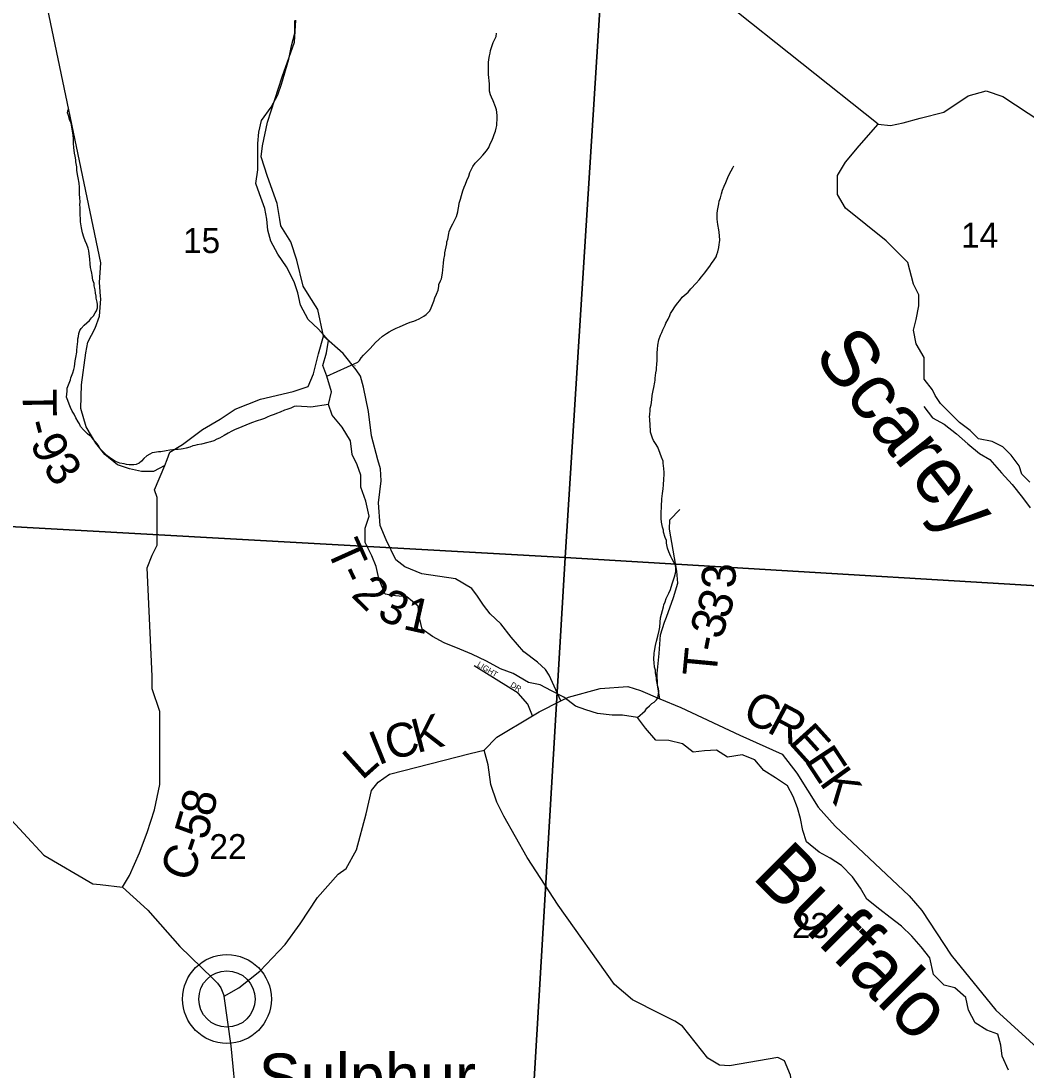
# Model space of a CAD drawing. Extents: x 0 to 34, y 0 to 22.
# Drawn here: x 6.056 to 7.74, y 18.037 to 19.794 of the extents above; entities that cross this region are included whole.
import ezdxf

# ---------------------------------------------------------------- set-up
doc = ezdxf.new("R2010")
doc.units = 0
for name, color, linetype in [('GM_X_County_Road', 7, 'Continuous'), ('GM_X_County_Road_Text', 7, 'Continuous'), ('GM_X_Minor_River', 7, 'Continuous'), ('GM_X_Minor_River_Text', 7, 'Continuous'), ('GM_X_Section', 7, 'Continuous'), ('GM_X_Section_Text', 7, 'Continuous'), ('GM_X_Township_Road', 7, 'Continuous'), ('GM_X_Township_Road_Text', 7, 'Continuous'), ('GM_X_Township_ROW', 7, 'Continuous'), ('GM_X_Township_Subdivision', 7, 'Continuous'), ('GM_X_Township_Subdivision_Text', 7, 'Continuous'), ('GM_X_Unincorporated', 7, 'Continuous'), ('GM_X_Unincorporated_Location', 7, 'Continuous'), ('GM_X_Unincorporated_Text', 7, 'Continuous')]:
    doc.layers.add(name, color=color, linetype=linetype)

msp = doc.modelspace()

# ---------------------------------------------------------------- linework, layer by layer
at = {"layer": 'GM_X_County_Road'}
for points in [[(6.2266, 18.3431), (6.238, 18.3629), (6.2549, 18.4009), (6.2675, 18.4347), (6.2802, 18.4727), (6.2886, 18.5149), (6.2886, 18.6373), (6.276, 18.6753), (6.276, 18.6964), (6.2675, 18.8779), (6.276, 18.899), (6.2844, 18.9159), (6.2844, 18.9961), (6.2802, 19.0087), (6.2972, 19.0494), (6.3013, 19.0594), (6.3055, 19.072), (6.3266, 19.0847), (6.3604, 19.11), (6.3899, 19.1269), (6.4152, 19.1438), (6.4574, 19.1607), (6.5123, 19.1733), (6.5376, 19.1818), (6.5461, 19.2029), (6.5545, 19.2366), (6.5629, 19.2661), (6.5536, 19.3108), (6.5392, 19.3335), (6.5289, 19.35), (6.5185, 19.3933), (6.5082, 19.4243), (6.4917, 19.4511), (6.4897, 19.4614), (6.4855, 19.4882), (6.469, 19.5336), (6.4587, 19.5666), (6.4608, 19.5851), (6.469, 19.6243), (6.4938, 19.7006), (6.5144, 19.7584), (6.5165, 19.7955)], [(6.1891, 18.3474), (6.2266, 18.3431), (6.2622, 18.3107), (6.2687, 18.3048), (6.3223, 18.2435), (6.377, 18.1905), (6.3855, 18.1823), (6.3913, 18.1746), (6.3965, 18.1604), (6.4212, 18.1743), (6.4566, 18.2027), (6.4991, 18.247), (6.5239, 18.2815), (6.5531, 18.3258), (6.5876, 18.3648), (6.6009, 18.3746), (6.6186, 18.4056), (6.6346, 18.4658), (6.6434, 18.5048), (6.6549, 18.519), (6.6735, 18.5323), (6.809, 18.5668), (6.8321, 18.5724), (6.8533, 18.5943), (6.9129, 18.6301), (6.9241, 18.6368), (6.9604, 18.655), (6.9737, 18.6616), (7.0268, 18.6758), (7.0729, 18.6793), (7.0941, 18.6723), (7.1264, 18.6587), (7.1614, 18.6439), (7.2606, 18.5979), (7.3315, 18.566), (7.3562, 18.5341), (7.3917, 18.4774), (7.42, 18.4456), (7.544, 18.3286), (7.5652, 18.3038), (7.6148, 18.2294), (7.6892, 18.1373), (7.7707, 18.0629)], [(7.3497, 17.9972), (7.3496, 17.9977), (7.3453, 18.028), (7.3354, 18.0523), (7.3241, 18.058), (7.243, 18.0436), (7.2267, 18.0451), (7.207, 18.0569), (7.1646, 18.1101), (7.1517, 18.1188), (7.126, 18.1314), (7.0809, 18.1546), (7.0506, 18.18), (6.9559, 18.313), (6.904, 18.3931), (6.865, 18.4619), (6.8533, 18.4858), (6.8431, 18.5151), (6.8389, 18.5481), (6.8321, 18.5724)], [(6.0263, 18.4702), (6.0945, 18.3967), (6.1768, 18.3489), (6.1891, 18.3474)], [(6.4177, 17.9792), (6.4082, 18.0772), (6.3965, 18.1604)]]:
    msp.add_lwpolyline(points, dxfattribs=at)
at = {"layer": 'GM_X_Minor_River'}
for points in [[(7.0639, 18.6314), (7.0465, 18.6315), (7.0223, 18.6338), (7.0026, 18.64), (6.9852, 18.6461), (6.9656, 18.6614), (6.9452, 18.6721), (6.9263, 18.682), (6.9066, 18.6859), (6.8809, 18.7012), (6.8597, 18.7088), (6.8363, 18.7218), (6.8114, 18.7333), (6.7917, 18.7417), (6.7653, 18.7524), (6.7456, 18.7631), (6.7282, 18.7754), (6.7238, 18.7944), (6.7216, 18.8141), (6.7027, 18.8294), (6.6838, 18.831), (6.6664, 18.834), (6.6559, 18.8599), (6.6514, 18.8804), (6.6439, 18.8979), (6.6327, 18.9207), (6.6328, 18.9443), (6.6397, 18.9648), (6.6337, 18.9898), (6.6255, 19.0134), (6.6256, 19.0331), (6.6196, 19.0506), (6.6113, 19.0681), (6.6084, 19.0909), (6.5941, 19.1137), (6.5775, 19.1335), (6.5715, 19.1518), (6.5762, 19.173), (6.5687, 19.1989), (6.562, 19.2171), (6.5681, 19.2383), (6.5712, 19.2588), (6.5546, 19.2779), (6.5373, 19.2939), (6.5245, 19.3182), (6.5201, 19.3387), (6.5141, 19.357), (6.5013, 19.3821), (6.4863, 19.4034), (6.475, 19.4254), (6.4698, 19.4437), (6.4683, 19.4619), (6.4646, 19.4801), (6.4556, 19.5045), (6.4496, 19.522), (6.4528, 19.5447), (6.453, 19.5887), (6.4545, 19.6077), (6.4592, 19.6274), (6.4752, 19.6494), (6.4866, 19.6706), (6.4928, 19.6881), (6.505, 19.7298), (6.5097, 19.7525), (6.5151, 19.7738), (6.5152, 19.795)], [(6.8409, 19.7354), (6.8422, 19.7399), (6.843, 19.7445), (6.845, 19.7513), (6.8474, 19.758), (6.8521, 19.7678), (6.853, 19.7735)], [(6.5687, 19.1989), (6.6205, 19.2223), (6.6233, 19.2256), (6.6264, 19.2298), (6.6302, 19.2342), (6.6337, 19.238), (6.6414, 19.2455), (6.6457, 19.2503), (6.6503, 19.2552), (6.6557, 19.2604), (6.6618, 19.266), (6.6684, 19.2704), (6.673, 19.2734), (6.6779, 19.2764), (6.6848, 19.2793), (6.6901, 19.2819), (6.7016, 19.287), (6.7085, 19.2895), (6.7142, 19.2913), (6.7184, 19.2931), (6.7233, 19.2953), (6.7314, 19.2994), (6.7348, 19.3024), (6.7414, 19.3083), (6.7437, 19.3136), (6.7457, 19.3189), (6.7481, 19.3249), (6.7497, 19.3302), (6.7521, 19.3363), (6.7549, 19.3434), (6.7561, 19.3491), (6.7565, 19.3525), (6.7593, 19.3589), (6.7605, 19.3623), (6.7622, 19.3714), (6.763, 19.3771), (6.7635, 19.3828), (6.764, 19.3881), (6.7649, 19.3945), (6.7661, 19.4021), (6.7662, 19.4055), (6.7674, 19.4108), (6.7695, 19.4206), (6.7695, 19.4241), (6.7711, 19.4286), (6.7732, 19.438), (6.7736, 19.4415), (6.7768, 19.449), (6.7795, 19.4543), (6.7823, 19.4599), (6.7858, 19.4663), (6.787, 19.4705), (6.7879, 19.4746), (6.7887, 19.4784), (6.7895, 19.4841), (6.7904, 19.4886), (6.7924, 19.4954), (6.7944, 19.5019), (6.7964, 19.5094), (6.7988, 19.5155), (6.8012, 19.5207), (6.8032, 19.5268), (6.8063, 19.5343), (6.8083, 19.54), (6.8107, 19.5445), (6.8134, 19.5502), (6.8173, 19.5558), (6.8243, 19.5629), (6.8301, 19.5692), (6.8362, 19.5763), (6.8401, 19.582), (6.8425, 19.588), (6.8449, 19.5933), (6.8472, 19.5989), (6.8492, 19.6038), (6.8512, 19.6095), (6.8524, 19.6144), (6.8533, 19.619), (6.8534, 19.6231), (6.8538, 19.6285), (6.8539, 19.6353), (6.8537, 19.6414), (6.8526, 19.6452), (6.8512, 19.6505), (6.8472, 19.6601), (6.8443, 19.6662), (6.8428, 19.6704), (6.8414, 19.6765), (6.8412, 19.683), (6.8409, 19.689), (6.8396, 19.7043), (6.8394, 19.7115), (6.8396, 19.7244), (6.8401, 19.7293), (6.8409, 19.7354)], [(6.1497, 19.2427), (6.1502, 19.248), (6.1515, 19.2571), (6.1516, 19.2617), (6.1524, 19.2658), (6.1532, 19.2704), (6.1548, 19.2753), (6.1572, 19.2787), (6.1622, 19.2843), (6.1664, 19.2884), (6.1711, 19.2925), (6.1745, 19.297), (6.1776, 19.3003), (6.1807, 19.3049), (6.1827, 19.3086), (6.1843, 19.3135), (6.1844, 19.3192), (6.1837, 19.323), (6.1823, 19.3295), (6.182, 19.3329), (6.1813, 19.3379), (6.1803, 19.3436), (6.1789, 19.3505), (6.1786, 19.3543), (6.1768, 19.36), (6.1754, 19.368), (6.1751, 19.3718), (6.1737, 19.3764), (6.1726, 19.3813), (6.1723, 19.387), (6.1717, 19.395), (6.1701, 19.4091), (6.169, 19.4133), (6.1665, 19.4194), (6.1636, 19.4259), (6.1614, 19.432), (6.1592, 19.4389), (6.1575, 19.4473), (6.1562, 19.4576), (6.1562, 19.4617), (6.1556, 19.4705), (6.1554, 19.4819), (6.1551, 19.4857), (6.1552, 19.4914), (6.155, 19.4971), (6.1543, 19.5043), (6.1541, 19.5119), (6.1541, 19.5157), (6.1535, 19.5225), (6.1522, 19.5313), (6.1511, 19.537), (6.1501, 19.5442), (6.1498, 19.5499), (6.1481, 19.5583), (6.1481, 19.5617), (6.1471, 19.5678), (6.1461, 19.5728), (6.1447, 19.5823), (6.1445, 19.5888), (6.1442, 19.596), (6.1436, 19.6025), (6.1426, 19.6097), (6.1408, 19.6196), (6.1405, 19.623), (6.1383, 19.6272), (6.1358, 19.6356), (6.1344, 19.6402), (6.1352, 19.6459)], [(7.1222, 19.232), (7.1219, 19.2381), (7.1224, 19.2442), (7.1229, 19.251), (7.125, 19.2597), (7.1277, 19.2676), (7.1297, 19.2721), (7.1313, 19.2767), (7.1356, 19.2846), (7.1364, 19.288), (7.1403, 19.2944), (7.1435, 19.3008), (7.1443, 19.3042), (7.1478, 19.3091), (7.1517, 19.3151), (7.1563, 19.3214), (7.1602, 19.3259), (7.1641, 19.3316), (7.1741, 19.3397), (7.1784, 19.3454), (7.1872, 19.3547), (7.1923, 19.3607), (7.1961, 19.3656), (7.2016, 19.3723), (7.2062, 19.3783), (7.2101, 19.3836), (7.2132, 19.3877), (7.2175, 19.3941), (7.2206, 19.399), (7.2218, 19.4027), (7.2238, 19.4076), (7.2254, 19.4148), (7.2259, 19.4194), (7.2267, 19.4232), (7.2271, 19.4269), (7.2265, 19.4342), (7.2259, 19.4403), (7.2256, 19.4441), (7.2234, 19.4532), (7.2228, 19.4623), (7.2225, 19.4673), (7.2226, 19.4718), (7.2231, 19.4764), (7.2256, 19.4877), (7.226, 19.4923), (7.228, 19.4979), (7.23, 19.5044), (7.2316, 19.5104), (7.234, 19.5172), (7.2368, 19.5236), (7.2415, 19.5349), (7.2459, 19.5428), (7.2486, 19.5481), (7.2505, 19.5515)], [(6.5715, 19.1518), (6.542, 19.1472), (6.5355, 19.1477), (6.5261, 19.1483), (6.5181, 19.1488), (6.5139, 19.1485), (6.5082, 19.1455), (6.5014, 19.1434), (6.4979, 19.1419), (6.4903, 19.139), (6.4842, 19.1364), (6.4804, 19.135), (6.4739, 19.1324), (6.4686, 19.1303), (6.4644, 19.1284), (6.459, 19.1266), (6.4522, 19.1245), (6.4426, 19.1208), (6.4327, 19.1172), (6.4194, 19.1113), (6.4148, 19.1095), (6.4094, 19.1069), (6.4033, 19.1036), (6.3964, 19.0999), (6.3888, 19.0955), (6.3842, 19.0933), (6.3796, 19.0907), (6.3735, 19.0889), (6.3693, 19.0879), (6.3587, 19.0854), (6.3515, 19.084), (6.3476, 19.0829), (6.3442, 19.0822), (6.3393, 19.0804), (6.3328, 19.0786), (6.3282, 19.0775), (6.3244, 19.0768), (6.3195, 19.0765), (6.315, 19.0762), (6.3104, 19.0759), (6.3059, 19.0753), (6.2994, 19.0738), (6.2903, 19.0725), (6.2869, 19.0722), (6.28, 19.0711), (6.2762, 19.0704), (6.272, 19.0686), (6.267, 19.0656), (6.262, 19.0612), (6.2582, 19.0567), (6.254, 19.0533), (6.2494, 19.0511), (6.2452, 19.0508), (6.2376, 19.0506), (6.2331, 19.051), (6.2289, 19.0522), (6.2221, 19.0535), (6.2165, 19.0555), (6.2127, 19.0574), (6.2067, 19.061), (6.2023, 19.0648), (6.1967, 19.0695), (6.1926, 19.0734), (6.1889, 19.0776), (6.1867, 19.0818), (6.1841, 19.086), (6.1807, 19.0899), (6.177, 19.0937), (6.1744, 19.0972), (6.1711, 19.0995), (6.1677, 19.1026), (6.1644, 19.1061), (6.161, 19.1092), (6.1558, 19.115), (6.1544, 19.1192), (6.1522, 19.1226), (6.1481, 19.1295), (6.1452, 19.1353), (6.1422, 19.1407), (6.1393, 19.1468), (6.1371, 19.1521), (6.1346, 19.1586), (6.1328, 19.164), (6.1337, 19.1742), (6.1338, 19.1788), (6.1358, 19.1844), (6.139, 19.1931), (6.1398, 19.1965), (6.1434, 19.2045), (6.145, 19.2105), (6.1458, 19.2147), (6.1467, 19.2196), (6.1471, 19.2245), (6.148, 19.2302), (6.1497, 19.2393), (6.1497, 19.2427)], [(7.0889, 18.6275), (7.1019, 18.6387), (7.1046, 18.6432), (7.1092, 18.647), (7.1131, 18.6507), (7.1169, 18.6533), (7.1208, 18.657), (7.1231, 18.6604), (7.1244, 18.6668), (7.1248, 18.6714), (7.1245, 18.6752), (7.1234, 18.6794), (7.122, 18.6847), (7.121, 18.6904), (7.1207, 18.6939), (7.1193, 18.7022), (7.119, 18.7064), (7.1176, 18.7118), (7.117, 18.7194), (7.1167, 18.7243), (7.1172, 18.7353), (7.1177, 18.7387), (7.119, 18.7478), (7.121, 18.7554), (7.1234, 18.7637), (7.1255, 18.7732), (7.1263, 18.7789), (7.1269, 18.7872), (7.1277, 18.7944), (7.1294, 18.8005), (7.1326, 18.8126), (7.1334, 18.8163), (7.1354, 18.8212), (7.137, 18.8269), (7.1413, 18.8356), (7.1441, 18.842), (7.1473, 18.8514), (7.1489, 18.8563), (7.1513, 18.8631), (7.1529, 18.8692), (7.1534, 18.8726), (7.1535, 18.8787), (7.152, 18.884), (7.1502, 18.8875), (7.1473, 18.8925), (7.1451, 18.897), (7.1418, 18.9047), (7.1396, 18.9112), (7.1379, 18.9196), (7.1376, 18.9241), (7.1354, 18.9287), (7.1329, 18.9379), (7.1326, 18.9413), (7.1312, 18.9459), (7.1294, 18.9543), (7.1288, 18.9607), (7.1285, 18.9653), (7.129, 18.9714), (7.1295, 18.9793), (7.1292, 18.985), (7.13, 18.9892), (7.1301, 18.9934), (7.131, 19.0025), (7.1319, 19.0104), (7.1328, 19.0173), (7.133, 19.0264), (7.1335, 19.0343), (7.1335, 19.0378), (7.1333, 19.0446), (7.1323, 19.0534), (7.132, 19.0568), (7.1295, 19.0633), (7.1273, 19.0694), (7.1229, 19.0801), (7.1192, 19.0862), (7.1159, 19.0916), (7.1141, 19.0954), (7.1123, 19.1), (7.1109, 19.1054), (7.1109, 19.1088), (7.1103, 19.116), (7.1097, 19.1274), (7.1094, 19.1308), (7.1095, 19.135), (7.1104, 19.1418), (7.1104, 19.1456), (7.1117, 19.1513), (7.113, 19.1596), (7.1139, 19.1668), (7.1155, 19.1748), (7.1164, 19.1801), (7.118, 19.1888), (7.1185, 19.1922), (7.1189, 19.196), (7.1194, 19.2002), (7.1198, 19.2047), (7.1207, 19.2096), (7.1207, 19.2131), (7.1216, 19.2184), (7.1221, 19.2259), (7.1222, 19.232)], [(6.6161, 19.2167), (6.6156, 19.2165)], [(7.5689, 19.1482), (7.5833, 19.1292), (7.6029, 19.1185), (7.6233, 19.1025), (7.6422, 19.0857), (7.6618, 19.0697), (7.6792, 19.0597), (7.6987, 19.0369), (7.7168, 19.0178), (7.7342, 18.9958), (7.747, 18.9783)], [(7.7105, 18.0366), (7.7, 18.0602), (7.6978, 18.0784), (7.6926, 18.0967), (7.6744, 18.1036), (7.6548, 18.1158), (7.6435, 18.1371), (7.639, 18.1584), (7.6209, 18.1744), (7.6028, 18.1791), (7.5847, 18.1966), (7.5787, 18.2247), (7.5644, 18.243), (7.5486, 18.2613), (7.5312, 18.2781), (7.5124, 18.2926), (7.495, 18.3056), (7.4731, 18.3231), (7.4626, 18.3414), (7.449, 18.3604), (7.4309, 18.3795), (7.412, 18.3917), (7.3932, 18.4016), (7.372, 18.4192), (7.366, 18.4382), (7.3623, 18.458), (7.3571, 18.4762), (7.3496, 18.4952), (7.3406, 18.5127), (7.3202, 18.5265), (7.3006, 18.5387), (7.2855, 18.5562), (7.2643, 18.5646), (7.2401, 18.5609), (7.2212, 18.5724), (7.2015, 18.5717), (7.1826, 18.5695), (7.1644, 18.5832), (7.1417, 18.5886), (7.1198, 18.5894), (7.1024, 18.6093), (7.0889, 18.6275), (7.0639, 18.6314)]]:
    msp.add_lwpolyline(points, dxfattribs=at)
at = {"layer": 'GM_X_Section'}
for points in [[(7.0324, 19.92), (6.9681, 18.8952), (5.8561, 18.9573), (5.9246, 19.9867)], [(8.1212, 19.8553), (8.0664, 18.8297), (6.9681, 18.8952), (7.0324, 19.92)], [(5.8561, 18.9573), (6.9681, 18.8952), (6.9079, 17.8893), (5.7907, 17.959)], [(6.9681, 18.8952), (8.0664, 18.8297), (8.012, 17.8219), (6.9079, 17.8893)]]:
    msp.add_lwpolyline(points, close=True, dxfattribs=at)
at = {"layer": 'GM_X_Township_Road'}
for points in [[(7.7466, 19.0215), (7.733, 19.0352), (7.7284, 19.0488), (7.7148, 19.067), (7.7012, 19.0806), (7.683, 19.0897), (7.6602, 19.0942), (7.6466, 19.1079), (7.6284, 19.1215), (7.5966, 19.1533), (7.5875, 19.1669), (7.583, 19.176), (7.5694, 19.1942), (7.5694, 19.2306), (7.5557, 19.2533), (7.5512, 19.276), (7.5557, 19.2942), (7.5603, 19.3169), (7.5603, 19.3351), (7.5512, 19.3532), (7.5421, 19.3896), (7.5058, 19.4259), (7.4376, 19.4805), (7.4239, 19.5032), (7.4239, 19.535), (7.4376, 19.5577), (7.4603, 19.585), (7.4921, 19.6213)], [(6.2972, 19.0494), (6.2784, 19.0396), (6.2583, 19.0392), (6.2383, 19.0441), (6.2182, 19.0506), (6.197, 19.0677), (6.1818, 19.087), (6.1652, 19.114), (6.1568, 19.1447), (6.1576, 19.1846), (6.1648, 19.2381), (6.1682, 19.256), (6.1807, 19.2795), (6.1879, 19.2996), (6.1898, 19.3285), (6.1894, 19.3332)], [(6.9604, 18.655), (6.9412, 18.6981), (6.9348, 18.7079), (6.9215, 18.7201), (6.8984, 18.7376), (6.8772, 18.7619), (6.8602, 18.7843), (6.8424, 18.801), (6.831, 18.8154), (6.8212, 18.8306), (6.8117, 18.8435), (6.7844, 18.8598), (6.7276, 18.8682), (6.6992, 18.8796), (6.6844, 18.8914), (6.6678, 18.9252), (6.6579, 18.9487), (6.6553, 18.9867), (6.6598, 19.0235), (6.6587, 19.044), (6.6542, 19.0592), (6.6436, 19.0991), (6.6383, 19.1397), (6.6303, 19.1807), (6.625, 19.1989), (6.6178, 19.2095), (6.5962, 19.2369), (6.5629, 19.2661)], [(7.1375, 18.7955), (7.1494, 18.8283), (7.1569, 18.8526), (7.1549, 18.8724), (7.1425, 18.9429), (7.1432, 18.9585), (7.1598, 18.9757)], [(7.1264, 18.6587), (7.1224, 18.6816), (7.122, 18.7009), (7.1252, 18.7348), (7.1274, 18.7659), (7.1345, 18.7872), (7.1375, 18.7954), (7.1375, 18.7955)]]:
    msp.add_lwpolyline(points, dxfattribs=at)
at = {"layer": 'GM_X_Township_ROW'}
for points in [[(7.4921, 19.6213), (7.2363, 19.8245), (6.9655, 20.0235), (6.7261, 20.2643), (6.563, 20.3945), (6.5017, 20.4356)], [(6.1894, 19.3332), (6.1876, 19.3562), (6.1898, 19.3892), (6.0906, 19.8649), (6.1237, 19.8842), (6.1299, 19.8887)], [(7.4921, 19.6213), (7.513, 19.6189), (7.5339, 19.6237), (7.5627, 19.6314), (7.6025, 19.6411), (7.6428, 19.6686), (7.6729, 19.677), (7.701, 19.6673), (7.7645, 19.6257)]]:
    msp.add_lwpolyline(points, dxfattribs=at)
at = {"layer": 'GM_X_Township_Subdivision'}
msp.add_lwpolyline([(6.9129, 18.6301), (6.9051, 18.6494), (6.889, 18.668), (6.8156, 18.7139)], dxfattribs=at)
at = {"layer": 'GM_X_Unincorporated'}
for radius in [0.0744, 0.0472]:
    msp.add_circle((6.4013, 18.1558), radius, dxfattribs=at)
at = {"layer": 'GM_X_Unincorporated_Location'}
msp.add_line((6.4013, 18.1558), (6.4013, 18.1558), dxfattribs=at)

# ---------------------------------------------------------------- texts
at = {"layer": 'GM_X_County_Road_Text'}
for s, rotation, p in [('C', 335.1199, (7.2621, 18.6233)), ('R', 331.8333, (7.3037, 18.6041)), ('K', 14.6874, (6.7195, 18.5674)), ('C', 15.6334, (6.6748, 18.5549)), ('E', 312.0311, (7.3407, 18.5852)), ('I', 22.1094, (6.6548, 18.5466)), ('E', 303.4892, (7.3678, 18.5554)), ('L', 41.8499, (6.6275, 18.521)), ('K', 305.6897, (7.3926, 18.518)), ('8', 78.9513, (6.3782, 18.4594)), ('5', 73.416, (6.3667, 18.4201)), ('-', 71.3134, (6.3586, 18.3958)), ('C', 67.9757, (6.3398, 18.3491))]:
    msp.add_text(s, height=0.0568, rotation=rotation, dxfattribs=at).set_placement(p)
at = {"layer": 'GM_X_Minor_River_Text'}
for s, height, rotation, p in [('Scarey', 0.09468, 308.1241, (7.3824, 19.2333)), ('Buffalo', 0.09471, 314.8733, (7.2791, 18.3596))]:
    msp.add_text(s, height=height, rotation=rotation, dxfattribs=at).set_placement(p)
at = {"layer": 'GM_X_Section_Text'}
for s, p in [('14', (7.631, 19.4143)), ('15', (6.3277, 19.4053)), ('22', (6.3719, 18.3901)), ('23', (7.3477, 18.2581))]:
    msp.add_text(s, height=0.04186, rotation=0, dxfattribs=at).set_placement(p)
at = {"layer": 'GM_X_Township_Road_Text'}
for s, rotation, p in [('T', 270.63, (6.0591, 19.1776)), ('-', 284.5573, (6.0616, 19.1203)), ('9', 294.3067, (6.0709, 19.0877)), ('3', 305.529, (6.0914, 19.0453)), ('T', 294.2171, (6.5672, 18.9098)), ('-', 296.1005, (6.5855, 18.8692)), ('3', 91.1693, (7.2541, 18.8437)), ('2', 315.2655, (6.6078, 18.8315)), ('3', 335.6918, (6.6507, 18.7944)), ('3', 72.2637, (7.2406, 18.7902)), ('1', 347.2279, (6.6944, 18.776)), ('3', 71.2116, (7.2289, 18.756)), ('-', 78.4472, (7.2247, 18.7349)), ('T', 84.6136, (7.221, 18.6942))]:
    msp.add_text(s, height=0.0568, rotation=rotation, dxfattribs=at).set_placement(p)
at = {"layer": 'GM_X_Township_Subdivision_Text'}
for s, rotation, p in [('LIGHT', 328.5701, (6.8195, 18.7137)), ('DR', 327.9922, (6.8753, 18.6796))]:
    msp.add_text(s, height=0.00947, rotation=rotation, dxfattribs=at).set_placement(p)
at = {"layer": 'GM_X_Unincorporated_Text'}
msp.add_text('Sulphur', height=0.07898, rotation=0, dxfattribs=at).set_placement((6.4544, 17.9855))

doc.saveas('drawing.dxf')
